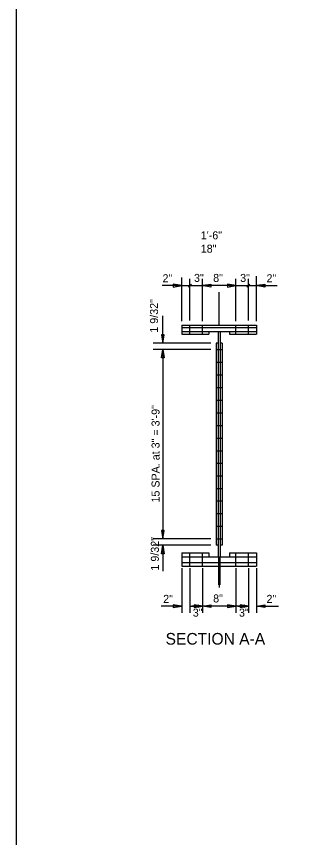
# Model space of a CAD drawing. Extents: x 4944 to 17449, y 3824 to 49087.
# Drawn here: x 10964 to 11394, y 9189 to 10371 of the extents above; entities that cross this region are included whole.
import ezdxf

# ---------------------------------------------------------------- set-up
doc = ezdxf.new("R2010")
doc.units = 0
for name, color, linetype in [('1', 7, 'Continuous'), ('36_S_LINES', 7, 'Continuous'), ('3A', 7, 'Continuous'), ('BEAM', 7, 'Continuous'), ('Level 14', 7, 'Continuous'), ('Level 25', 7, 'Continuous')]:
    doc.layers.add(name, color=color, linetype=linetype)

msp = doc.modelspace()

# ---------------------------------------------------------------- linework, layer by layer
at = {"layer": '1'}
for points in [[(11213.8, 9913.5), (11213.8, 9926.6)], [(11232, 9913.5), (11232, 9926.6)], [(11280, 9913.5), (11280, 9926.6)], [(11298.2, 9913.5), (11298.2, 9926.6)], [(11251.5, 9891.5), (11260.5, 9891.5)], [(11251.5, 9873.3), (11260.5, 9873.3)], [(11251.5, 9855.1), (11260.5, 9855.1)], [(11251.5, 9836.9), (11260.5, 9836.9)], [(11251.5, 9818.8), (11260.5, 9818.8)], [(11251.5, 9800.6), (11260.5, 9800.6)], [(11251.5, 9782.4), (11260.5, 9782.4)], [(11251.5, 9764.2), (11260.5, 9764.2)], [(11251.5, 9746), (11260.5, 9746)], [(11251.5, 9728.2), (11260.5, 9728.2)], [(11251.5, 9710), (11260.5, 9710)], [(11251.5, 9691.8), (11260.5, 9691.8)], [(11251.5, 9673.6), (11260.5, 9673.6)], [(11251.5, 9655.4), (11260.5, 9655.4)], [(11251.5, 9637.2), (11260.5, 9637.2)], [(11251.5, 9619), (11260.5, 9619)], [(11213.8, 9579.8), (11213.8, 9598.9)], [(11232, 9579.8), (11232, 9598.9)], [(11280, 9579.8), (11280, 9598.9)], [(11298.2, 9579.8), (11298.2, 9598.9)]]:
    msp.add_lwpolyline(points, dxfattribs=at)
at = {"layer": '36_S_LINES'}
for p, q in [((11310, 9932.2), (11310, 9997)), ((11202, 9932.2), (11202, 9995.3)), ((11216.1, 9985.7), (11211.6, 9981.2)), ((11300.4, 9985.7), (11295.9, 9981.2)), ((11202, 9983.5), (11173.9, 9983.5)), ((11202, 9983.5), (11232, 9983.5)), ((11280, 9983.5), (11232, 9983.5)), ((11280, 9983.5), (11310, 9983.5)), ((11310, 9983.5), (11339.8, 9983.5)), ((11174.8, 9900.6), (11174.8, 9940)), ((11243.9, 9900.6), (11160.7, 9900.6)), ((11174.8, 9891.5), (11174.8, 9619)), ((11243.9, 9609.9), (11160.7, 9609.9)), ((11174.8, 9609.9), (11174.8, 9572.4)), ((11202, 9576.7), (11202, 9512.6)), ((11310, 9576.7), (11310, 9512.6)), ((11202, 9522.2), (11172.2, 9522.2)), ((11213.8, 9522.2), (11232, 9522.2)), ((11280, 9522.2), (11232, 9522.2)), ((11298.2, 9522.2), (11280, 9522.2)), ((11310, 9522.2), (11341.5, 9522.2))]:
    msp.add_line(p, q, dxfattribs=at)
for points in [[(11189.9, 9985.5), (11189.9, 9981.4), (11202, 9983.5)], [(11194, 9982.5), (11194, 9984.5), (11202, 9983.5)], [(11194, 9984.5), (11194, 9982.5), (11202, 9983.5)], [(11244.1, 9985.5), (11244.1, 9981.4), (11232, 9983.5)], [(11240, 9982.5), (11240, 9984.5), (11232, 9983.5)], [(11240, 9984.5), (11240, 9982.5), (11232, 9983.5)], [(11267.9, 9985.5), (11267.9, 9981.4), (11280, 9983.5)], [(11272, 9982.5), (11272, 9984.5), (11280, 9983.5)], [(11272, 9984.5), (11272, 9982.5), (11280, 9983.5)], [(11322.1, 9985.5), (11322.1, 9981.4), (11310, 9983.5)], [(11318, 9982.5), (11318, 9984.5), (11310, 9983.5)], [(11318, 9984.5), (11318, 9982.5), (11310, 9983.5)], [(11176.8, 9912.8), (11172.7, 9912.8), (11174.8, 9900.6)], [(11176.8, 9879.4), (11172.7, 9879.4), (11174.8, 9891.5)], [(11176.8, 9631.1), (11172.7, 9631.1), (11174.8, 9619)], [(11176.8, 9597.8), (11172.7, 9597.8), (11174.8, 9609.9)], [(11189.9, 9524.3), (11189.9, 9520.2), (11202, 9522.2)], [(11194, 9523.2), (11194, 9521.2), (11202, 9522.2)], [(11225.9, 9524.3), (11225.9, 9520.2), (11213.8, 9522.2)], [(11221.8, 9523.2), (11221.8, 9521.2), (11213.8, 9522.2)], [(11219.9, 9524.3), (11219.9, 9520.2), (11232, 9522.2)], [(11224, 9523.2), (11224, 9521.2), (11232, 9522.2)], [(11244.1, 9524.3), (11244.1, 9520.2), (11232, 9522.2)], [(11240, 9523.2), (11240, 9521.2), (11232, 9522.2)], [(11267.9, 9524.3), (11267.9, 9520.2), (11280, 9522.2)], [(11272, 9523.2), (11272, 9521.2), (11280, 9522.2)], [(11292.1, 9524.3), (11292.1, 9520.2), (11280, 9522.2)], [(11288, 9523.2), (11288, 9521.2), (11280, 9522.2)], [(11286.1, 9524.3), (11286.1, 9520.2), (11298.2, 9522.2)], [(11290.2, 9523.2), (11290.2, 9521.2), (11298.2, 9522.2)], [(11322.1, 9524.3), (11322.1, 9520.2), (11310, 9522.2)], [(11318, 9523.2), (11318, 9521.2), (11310, 9522.2)]]:
    msp.add_lwpolyline(points, close=True, dxfattribs=at)
at = {"layer": '3A'}
for p, q in [((11213.8, 9933.3), (11213.8, 9993.1)), ((11232, 9932.5), (11232, 9993.1)), ((11280, 9932.5), (11280, 9993.1)), ((11298.2, 9933.3), (11298.2, 9993.1)), ((11243.9, 9891.5), (11160.7, 9891.5)), ((11243.9, 9619), (11160.7, 9619)), ((11213.8, 9576.7), (11213.8, 9512.6)), ((11232, 9576.7), (11232, 9512.6)), ((11280, 9576.7), (11280, 9512.6)), ((11298.2, 9576.7), (11298.2, 9512.6))]:
    msp.add_line(p, q, dxfattribs=at)
at = {"layer": 'DEFPOINTS'}
for p, q in [((11256, 9926.6), (11256, 9974)), ((11255.1, 9593.3), (11255.1, 9552.8)), ((11256.9, 9593.3), (11256.9, 9552.8)), ((11256, 9579.8), (11256, 9552.8)), ((11256, 9574), (11256, 9549.2))]:
    msp.add_line(p, q, dxfattribs=at)
at = {"layer": 'Level 14'}
msp.add_lwpolyline([(13987.8, 8476.1), (10963.7, 8476.1), (10963.7, 10492.1), (13987.8, 10492.1)], close=True, dxfattribs=at)
at = {"layer": 'Level 25'}
for p, q in [((11202, 9926.6), (11310, 9926.6)), ((11202, 9926.6), (11202, 9913.5)), ((11310, 9926.6), (11310, 9913.5)), ((11202, 9923.3), (11310, 9923.3)), ((11202, 9917.3), (11310, 9917.3)), ((11202, 9913.5), (11241.1, 9913.5)), ((11241.1, 9917.3), (11241.1, 9913.5)), ((11254.5, 9917.3), (11254.5, 9593.3)), ((11257.5, 9917.3), (11257.5, 9593.3)), ((11270.9, 9917.3), (11270.9, 9913.5)), ((11270.9, 9913.5), (11310, 9913.5)), ((11251.5, 9900.6), (11251.5, 9609.9)), ((11254.5, 9900.6), (11251.5, 9900.6)), ((11260.5, 9900.6), (11257.5, 9900.6)), ((11260.5, 9900.6), (11260.5, 9609.9)), ((11254.5, 9609.9), (11251.5, 9609.9)), ((11260.5, 9609.9), (11257.5, 9609.9)), ((11202, 9598.9), (11241.1, 9598.9)), ((11202, 9598.9), (11202, 9579.8)), ((11241.1, 9598.9), (11241.1, 9593.3)), ((11270.9, 9598.9), (11310, 9598.9)), ((11270.9, 9598.9), (11270.9, 9593.3)), ((11310, 9598.9), (11310, 9579.8)), ((11202, 9593.3), (11310, 9593.3)), ((11202, 9585), (11310, 9585)), ((11202, 9579.8), (11310, 9579.8))]:
    msp.add_line(p, q, dxfattribs=at)

# ---------------------------------------------------------------- texts
at = {"layer": '3A'}
for s, p in [('2"', (11174.4, 9988.3)), ('3"', (11219.8, 9988.8)), ('8"', (11247.4, 9988.8)), ('3"', (11286.3, 9988.8)), ('2"', (11324.3, 9988.3)), ('2"', (11175.4, 9527)), ('8"', (11247.4, 9527.6)), ('2"', (11324.3, 9527)), ('3"', (11218, 9507.2)), ('3"', (11284.6, 9507.2))]:
    msp.add_text(s, height=11.52, dxfattribs=at).set_placement(p)
for s, p in [('1 9/32"', (11167.9, 9915.8)), ('15 SPA. at 3" = 3\'-9"', (11170.1, 9671.4)), ('1 9/32"', (11169.1, 9573.5))]:
    msp.add_text(s, height=11.52, rotation=90, dxfattribs=at).set_placement(p)
at = {"layer": 'BEAM'}
msp.add_text('SECTION A-A', height=16.8, dxfattribs=at).set_placement((11178.8, 9466.9))
at = {"layer": 'DEFPOINTS'}
for s, p in [('1\'-6"', (11229.5, 10050.1)), ('18"', (11229.5, 10030.9))]:
    msp.add_text(s, height=11.52, dxfattribs=at).set_placement(p)

doc.saveas('drawing.dxf')
